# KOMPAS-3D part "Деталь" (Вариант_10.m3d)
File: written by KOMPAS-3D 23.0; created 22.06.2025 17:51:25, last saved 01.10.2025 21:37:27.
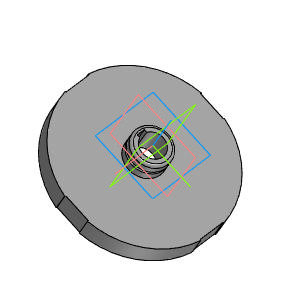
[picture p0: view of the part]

Document properties: Автор: admin; Организация: MGTU; Полное имя файла: C:\Users\ssafo\OneDrive\Desktop\ЦД_Грант\Решенные варианты\Вариант_10.m3d

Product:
- Part/product: Деталь
    Масса: 0.905238
    Форматы листов документа: A4

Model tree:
1. Эскиз:1
2. Элемент вращения:1
     Угол 1 = 360
3. Эскиз:6  (with: Элемент вращения:1)
4. Элемент выдавливания:5
5. Эскиз:7  (with: Элемент вращения:1)
6. Эскиз:8  (with: Элемент выдавливания:5, Элемент вращения:1)
7. Элемент выдавливания:7  (with: Элемент вращения:1)
     Расстояние 2 = 15
8. Эскиз:9  (with: Элемент вращения:1)
9. Элемент выдавливания:8
     Расстояние 1 = 10; Расстояние 2 = 10
10. Массив по концентрической сетке:2  (with: Элемент выдавливания:8, Эскиз:9, Элемент вращения:1)  (4 pattern instances)
     Шаг 2 = 360
11. Скругление:5  (with: Элемент вращения:1)
     Радиус = 2
12. Эскиз:10  (with: Элемент вращения:1)
13. Элемент выдавливания:9
     Расстояние 2 = 8
14. Эскиз:11  (with: Элемент выдавливания:9)
15. Элемент выдавливания:10
     Расстояние 2 = 2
